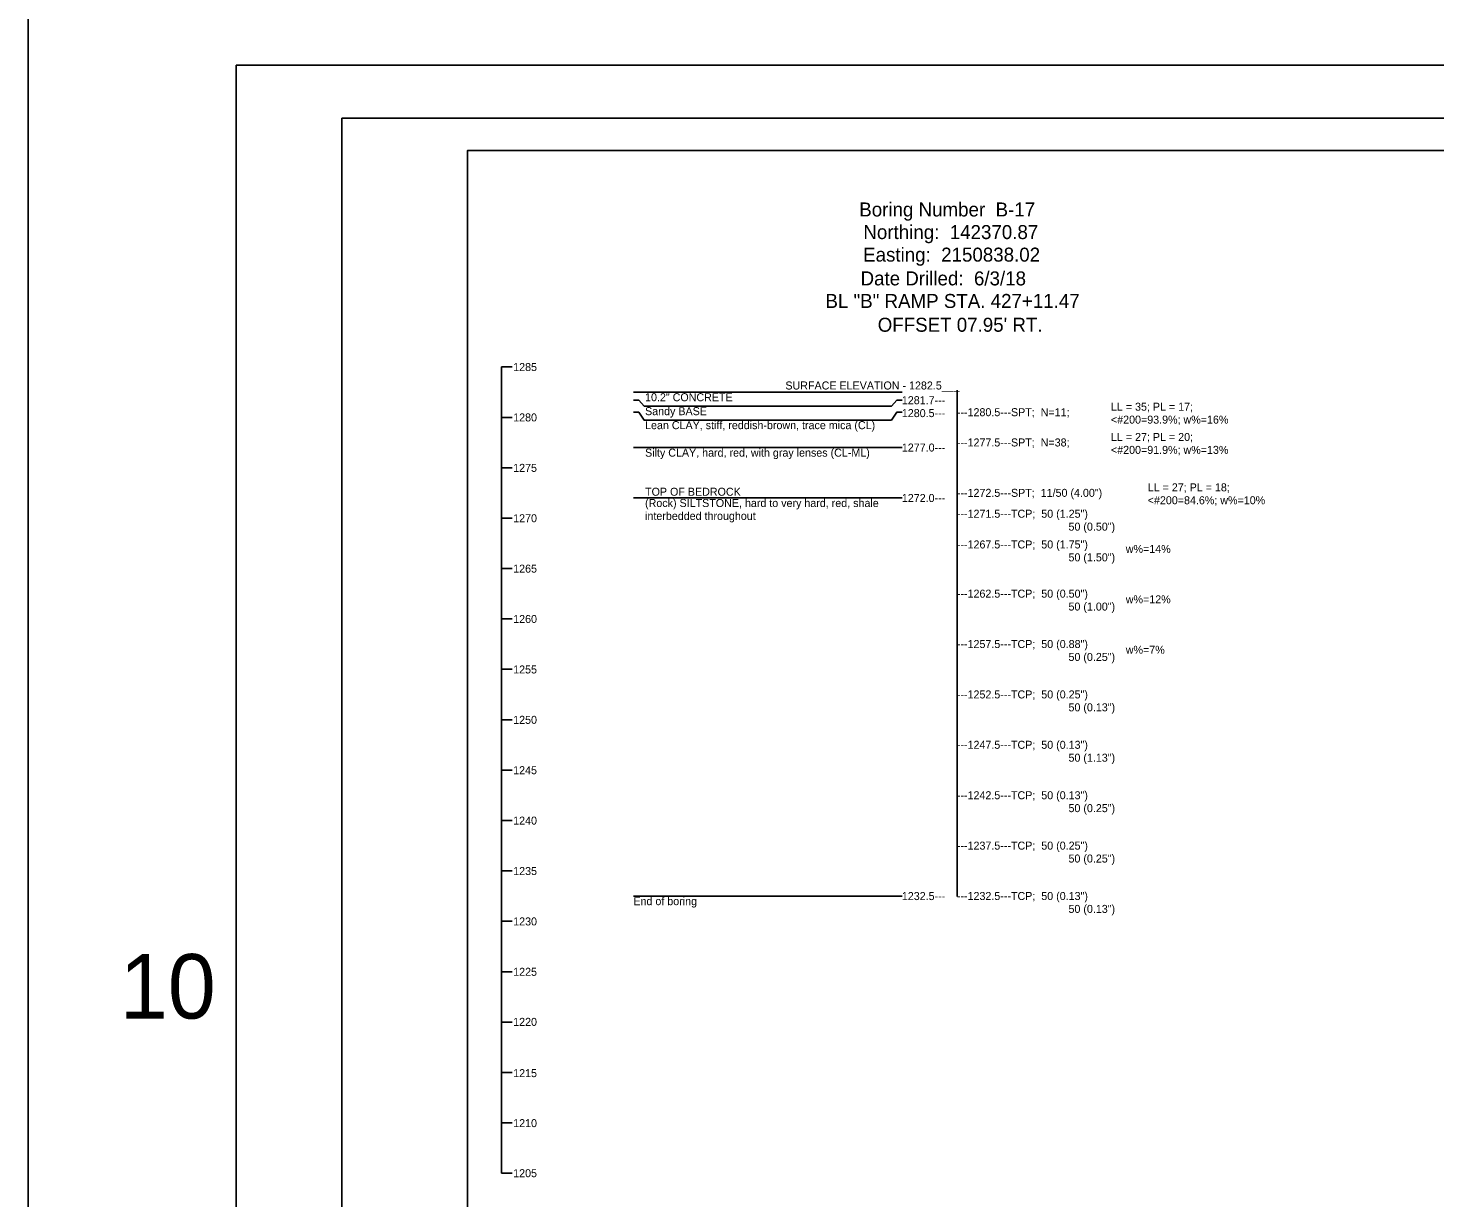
# Model space of a CAD drawing. Extents: x 2150162 to 2150245, y 143729 to 143865.
# Drawn here: x 2150203.4 to 2150225.21, y 143743.1 to 143761.23 of the extents above; entities that cross this region are included whole.
import ezdxf

# ---------------------------------------------------------------- set-up
doc = ezdxf.new("R2010")
doc.units = 0
for name, color, linetype in [('Default', 7, 'Continuous'), ('S', 7, 'Continuous'), ('SHT_Plot_Shape_Full', 7, 'Continuous'), ('SHT_Plot_Shape_Half', 7, 'Continuous'), ('SHT_Sheet_Border', 7, 'Continuous')]:
    doc.layers.add(name, color=color, linetype=linetype)

msp = doc.modelspace()

# ---------------------------------------------------------------- linework, layer by layer
at = {"layer": 'Default'}
msp.add_line((2150210.741, 143743.48), (2150210.741, 143755.98), dxfattribs=at)
for points in [[(2150210.741, 143755.98), (2150210.907, 143755.98)], [(2150212.785, 143755.589), (2150216.951, 143755.589)], [(2150217.801, 143755.618), (2150217.801, 143747.77)], [(2150212.785, 143755.464), (2150212.868, 143755.464), (2150212.951, 143755.372), (2150216.785, 143755.372), (2150216.868, 143755.464), (2150216.951, 143755.464)], [(2150212.785, 143755.277), (2150212.868, 143755.277), (2150212.951, 143755.156), (2150216.785, 143755.156), (2150216.868, 143755.277), (2150216.951, 143755.277)], [(2150210.741, 143755.198), (2150210.907, 143755.198)], [(2150212.785, 143754.73), (2150216.951, 143754.73)], [(2150210.741, 143754.417), (2150210.907, 143754.417)], [(2150212.785, 143753.948), (2150216.951, 143753.948)], [(2150210.741, 143753.636), (2150210.907, 143753.636)], [(2150210.741, 143753.636), (2150210.907, 143753.636)], [(2150210.741, 143752.855), (2150210.907, 143752.855)], [(2150210.741, 143752.073), (2150210.907, 143752.073)], [(2150210.741, 143751.292), (2150210.907, 143751.292)], [(2150210.741, 143750.511), (2150210.907, 143750.511)], [(2150210.741, 143749.73), (2150210.907, 143749.73)], [(2150210.741, 143748.948), (2150210.907, 143748.948)], [(2150210.741, 143748.167), (2150210.907, 143748.167)], [(2150212.785, 143747.777), (2150216.951, 143747.777)], [(2150210.741, 143747.386), (2150210.907, 143747.386)], [(2150210.741, 143746.605), (2150210.907, 143746.605)], [(2150210.741, 143745.823), (2150210.907, 143745.823)], [(2150210.741, 143745.042), (2150210.907, 143745.042)], [(2150210.741, 143744.261), (2150210.907, 143744.261)], [(2150210.741, 143743.48), (2150210.907, 143743.48)]]:
    msp.add_lwpolyline(points, dxfattribs=at)
at = {"layer": 'S'}
for points in [[(2150203.404, 143865.061), (2150245.24, 143865.061), (2150245.24, 143729.315), (2150203.404, 143729.315)], [(2150161.568, 143784.341), (2150203.404, 143784.341), (2150203.404, 143729.315), (2150161.568, 143729.315)]]:
    msp.add_lwpolyline(points, close=True, dxfattribs=at)
at = {"layer": 'SHT_Plot_Shape_Full'}
msp.add_lwpolyline([(2150206.628, 143760.659), (2150242.628, 143760.659), (2150242.628, 143736.659), (2150206.628, 143736.659)], close=True, dxfattribs=at)
at = {"layer": 'SHT_Plot_Shape_Half'}
msp.add_lwpolyline([(2150208.265, 143759.835), (2150242.265, 143759.835), (2150242.265, 143737.835), (2150208.265, 143737.835)], close=True, dxfattribs=at)
at = {"layer": 'SHT_Sheet_Border'}
msp.add_lwpolyline([(2150241.715, 143738.335), (2150210.215, 143738.335), (2150210.215, 143759.335), (2150241.715, 143759.335)], close=True, dxfattribs=at)

# ---------------------------------------------------------------- texts
at = {"layer": 'Default'}
for s, height, p in [('Boring Number  B-17', 0.217, (2150216.286, 143758.312)), ('Northing:  142370.87', 0.217, (2150216.35, 143757.962)), ('Easting:  2150838.02', 0.217, (2150216.346, 143757.612)), ('Date Drilled:  6/3/18', 0.217, (2150216.306, 143757.244)), ('BL "B" RAMP STA. 427+11.47', 0.217, (2150215.762, 143756.894)), ("OFFSET 07.95' RT.", 0.217, (2150216.572, 143756.525)), ('1285', 0.124, (2150210.922, 143755.916)), ('SURFACE ELEVATION - 1282.5___', 0.124, (2150215.141, 143755.63)), ('10.2" CONCRETE', 0.124, (2150212.966, 143755.448)), ('1281.7---', 0.124, (2150216.946, 143755.402)), ('1280', 0.124, (2150210.922, 143755.135)), ('Sandy BASE', 0.124, (2150212.966, 143755.232)), ('1280.5---', 0.124, (2150216.946, 143755.202)), ('---1280.5---SPT;  N=11;', 0.124, (2150217.799, 143755.216)), ('LL = 35; PL = 17;', 0.124, (2150220.187, 143755.301)), ('Lean CLAY, stiff, reddish-brown, trace mica (CL)', 0.124, (2150212.966, 143755.015)), ('<#200=93.9%; w%=16%', 0.124, (2150220.187, 143755.101)), ('---1277.5---SPT;  N=38;', 0.124, (2150217.799, 143754.747)), ('LL = 27; PL = 20;', 0.124, (2150220.187, 143754.832)), ('Silty CLAY, hard, red, with gray lenses (CL-ML)', 0.124, (2150212.966, 143754.589)), ('1277.0---', 0.124, (2150216.946, 143754.668)), ('<#200=91.9%; w%=13%', 0.124, (2150220.187, 143754.632)), ('1275', 0.124, (2150210.922, 143754.353)), ('LL = 27; PL = 18;', 0.124, (2150220.757, 143754.051)), ('TOP OF BEDROCK', 0.124, (2150212.966, 143753.983)), ('1272.0---', 0.124, (2150216.946, 143753.886)), ('---1272.5---SPT;  11/50 (4.00")', 0.124, (2150217.799, 143753.966)), ('<#200=84.6%; w%=10%', 0.124, (2150220.757, 143753.851)), ('(Rock) SILTSTONE, hard to very hard, red, shale', 0.124, (2150212.966, 143753.808)), ('interbedded throughout', 0.124, (2150212.966, 143753.608)), ('---1271.5---TCP;  50 (1.25")', 0.124, (2150217.799, 143753.642)), ('1270', 0.124, (2150210.922, 143753.572)), ('50 (0.50")', 0.124, (2150219.529, 143753.442)), ('---1267.5---TCP;  50 (1.75")', 0.124, (2150217.799, 143753.166)), ('50 (1.50")', 0.124, (2150219.529, 143752.966)), ('w%=14%', 0.124, (2150220.417, 143753.096)), ('1265', 0.124, (2150210.922, 143752.791)), ('---1262.5---TCP;  50 (0.50")', 0.124, (2150217.799, 143752.403)), ('w%=12%', 0.124, (2150220.417, 143752.315)), ('50 (1.00")', 0.124, (2150219.529, 143752.203)), ('1260', 0.124, (2150210.922, 143752.01)), ('---1257.5---TCP;  50 (0.88")', 0.124, (2150217.799, 143751.622)), ('50 (0.25")', 0.124, (2150219.529, 143751.422)), ('w%=7%', 0.124, (2150220.417, 143751.533)), ('1255', 0.124, (2150210.922, 143751.228)), ('---1252.5---TCP;  50 (0.25")', 0.124, (2150217.799, 143750.841)), ('50 (0.13")', 0.124, (2150219.529, 143750.641)), ('1250', 0.124, (2150210.922, 143750.447)), ('---1247.5---TCP;  50 (0.13")', 0.124, (2150217.799, 143750.06)), ('50 (1.13")', 0.124, (2150219.529, 143749.86)), ('1245', 0.124, (2150210.922, 143749.666)), ('---1242.5---TCP;  50 (0.13")', 0.124, (2150217.799, 143749.278)), ('50 (0.25")', 0.124, (2150219.529, 143749.078)), ('1240', 0.124, (2150210.922, 143748.885)), ('---1237.5---TCP;  50 (0.25")', 0.124, (2150217.799, 143748.497)), ('50 (0.25")', 0.124, (2150219.529, 143748.297)), ('1235', 0.124, (2150210.922, 143748.103)), ('---1232.5---TCP;  50 (0.13")', 0.124, (2150217.799, 143747.716)), ('End of boring', 0.124, (2150212.785, 143747.636)), ('1232.5---', 0.124, (2150216.946, 143747.715)), ('50 (0.13")', 0.124, (2150219.529, 143747.516)), ('1230', 0.124, (2150210.922, 143747.322)), ('1225', 0.124, (2150210.922, 143746.541)), ('1220', 0.124, (2150210.922, 143745.765)), ('1215', 0.124, (2150210.922, 143744.97)), ('1210', 0.124, (2150210.922, 143744.195)), ('1205', 0.124, (2150210.922, 143743.419))]:
    msp.add_text(s, height=height, dxfattribs=at).set_placement(p)
at = {"layer": 'S'}
msp.add_text('10', height=1, dxfattribs=at).set_placement((2150204.825, 143745.878))

doc.saveas('drawing.dxf')
